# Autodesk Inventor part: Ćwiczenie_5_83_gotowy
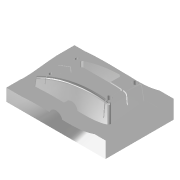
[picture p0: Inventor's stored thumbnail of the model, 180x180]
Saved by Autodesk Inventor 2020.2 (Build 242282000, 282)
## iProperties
Created: 2006-08
Part Number: Ćwiczenie_5_83_gotowy
Document SubType Name: Modeling
Designer: F.Stasiak
Density: 1 g/cm^3
Material: Ogólny
Appearance: Chrom — polerowany
Manager: www.cadconsulting.pl
Company: Fabian Stasiak CAD Consulting
Author: F.Stasiak
Subject: Zbiór ćwiczeń. Autodesk Inventor 2020. Kurs podstawowy
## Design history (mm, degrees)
derived "Obudowa_Front_v2.ipt"
sketch "Szkic2"
  geometry: L1 (-80, 55)-(80, 55); L2 (80, 55)-(80, -55); L3 (80, -55)-(-80, -55); L4 (-80, -55)-(-80, 55); 1 further point
  constraints: 8 end point, 2 parallel, 1 horizontal, 1 perpendicular
  dimensions: "d1" = 160 distance of L2.end L3.end; "d2" = 110 distance of L3.end L1.start; "d3" = 55 distance from line of point (0, 0) L3 (= 0.5 x d2); "d4" = 80 distance from line of point (0, 0) L4 (= 0.5 x d1)
feature "Powierzchnia boczna płyty" sketch "Szkic2" dims "d5" = 35, "d6" = 0
feature "Spód" dims "d52" = 0, "d53" = 0, "d54" = 0, "d55" = 0, "d56" = 0
feature "Zszyj powierzchnię4"
feature "Utnij1"
feature "Rzeźbienie1"
node "Bryła1"
node "Korpusy bryłowe"
node "Korpusy powierzchniowe"
body "Srf2"
body "Srf3"
feature "Pozyskana bryła konstrukcyjna3"
body "Srf1"
sketch "Szkic15"
  geometry: A1 r 10.5 centre (80, 17.5) between (69.788, 15.057) and (90.061, 14.496) reference; 4 further points
  constraints: 3 other
node "Krawędzie5"
body "Srf4"
sketch "Szkic16"
  geometry: 4 further points
  constraints: 2 other
node "Krawędzie6"
body "Srf5"
sketch "Szkic17"
  geometry: L1 (-9.034, 80.529)-(-9.034, 110) reference; 1 further point
node "Krawędzie7"
body "Srf6"
sketch "Szkic18"
  geometry: 4 further points
  constraints: 2 other
node "Krawędzie8"
body "Srf7"
sketch "Szkic19"
  geometry: L1 (-5.748, 24.528)-(-5.748, 0) reference; 1 further point
node "Krawędzie9"
body "Srf8"
sketch "Szkic20"
  geometry: 4 further points
  constraints: 2 other
node "Krawędzie10"
body "Srf9"
sketch "Szkic21"
  geometry: L1 (11.029, 29.296)-(11.029, 0) reference; 1 further point
node "Krawędzie11"
body "Srf10"
sketch "Szkic22"
  geometry: L1 (15.283, 86.306)-(15.283, 110) reference; 1 further point
node "Krawędzie12"
body "Srf11"
body "Srf12"
feature "PowWyciągnięciaZłożonego5" dims "d58" = 0, "d59" = 90 deg, "d60" = 0, "d61" = 90 deg
feature "PowWyciągnięciaZłożonego6" dims "d62" = 0, "d63" = 90 deg, "d64" = 0, "d65" = 90 deg
feature "PowWyciągnięciaZłożonego7" dims "d66" = 0, "d67" = 90 deg, "d68" = 0, "d69" = 90 deg
feature "PowWyciągnięciaZłożonego8" dims "d70" = 0, "d71" = 90 deg, "d72" = 0, "d73" = 90 deg
feature "PowWyciągnięciaZłożonego9" dims "d74" = 0, "d75" = 90 deg, "d76" = 0, "d77" = 90 deg
feature "PowWyciągnięciaZłożonego10" dims "d78" = 0, "d79" = 90 deg, "d80" = 0, "d81" = 90 deg
feature "PowWyciągnięciaZłożonego11" dims "d82" = 0, "d83" = 90 deg, "d84" = 0, "d85" = 90 deg
feature "PowWyciągnięciaZłożonego12" dims "d86" = 0, "d87" = 90 deg, "d88" = 0, "d89" = 90 deg
